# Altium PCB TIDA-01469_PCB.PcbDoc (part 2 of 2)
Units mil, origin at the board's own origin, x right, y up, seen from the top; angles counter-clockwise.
Board outline 2303.15 x 3751.97 mil, 4 copper layers (Layer 1 - Top Layer, Layer 2 - GND, Layer 3 - PWR, Layer 4 - Bottom Layer), stack 61.634 mil thick; 66 components, 33 nets, 183 pads, 184 vias.
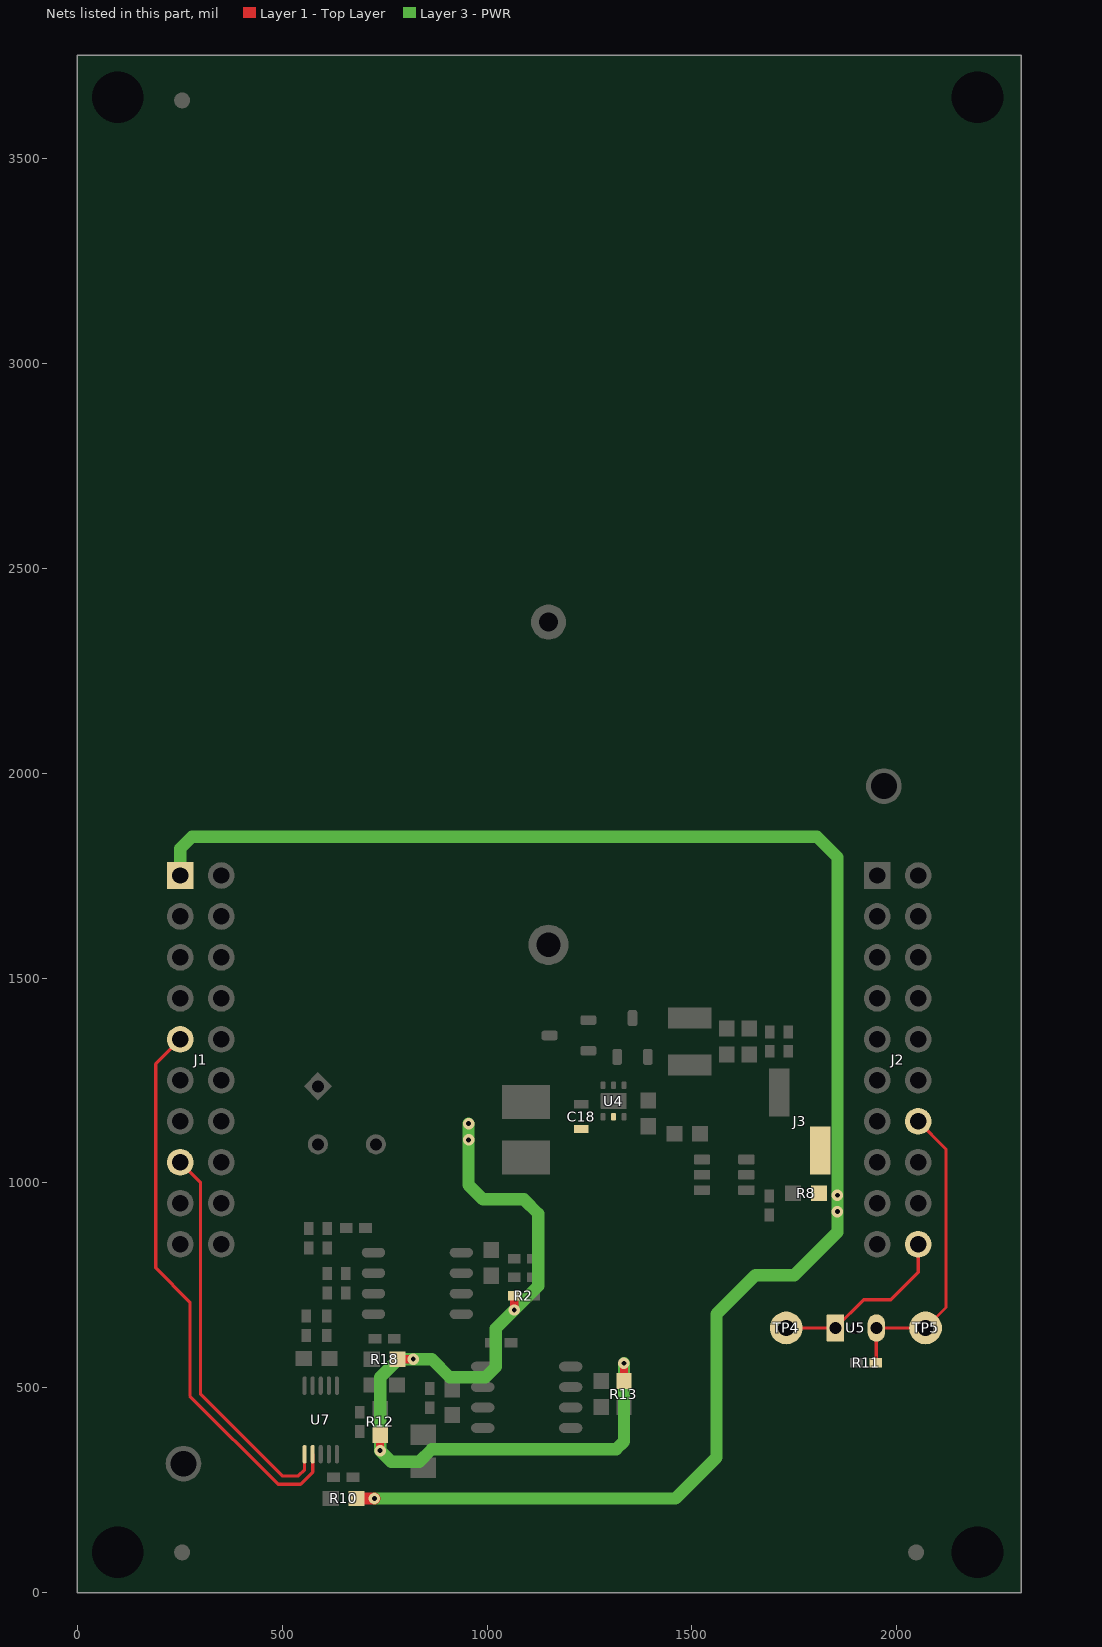
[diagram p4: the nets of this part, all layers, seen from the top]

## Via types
v1: diameter 28, hole 12, Layer 1 - Top Layer to Layer 4 - Bottom Layer, tented both sides, 178 vias
v2: diameter 50, hole 28, Layer 1 - Top Layer to Layer 4 - Bottom Layer, 4 vias
v3: diameter 19.68, hole 7.87, Layer 1 - Top Layer to Layer 4 - Bottom Layer, 2 vias

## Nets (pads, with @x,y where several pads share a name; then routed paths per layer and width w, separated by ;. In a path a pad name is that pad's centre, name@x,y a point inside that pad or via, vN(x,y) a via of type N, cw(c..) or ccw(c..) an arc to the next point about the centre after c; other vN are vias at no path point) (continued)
SPI_CS: J1.15 U7.6 | length 967.5
  Layer 1 - Top Layer w8: J1.15@251.3,1050.39 301,1000.69 301,484 500,285 539.8,285 554.8,300 U7.6@554.8,338.11
SPI_SDI: J1.9 U7.7 | length 1374.3
  Layer 1 - Top Layer w8: J1.9@251.3,1350.39 191.31,1290.41 191.31,792.7 275,709.02 275,480 490,265 545,265 574.49,294.49 U7.7@574.49,338.11
TEMP_IN: J2.20 TP4.1 U5.1 | length 446.7
  Layer 1 - Top Layer w8: TP4.1@1730.01,646.07 U5.1@1850.01,646.07 1918.94,715 1985,715 2052.09,782.09 J2.20@2052.09,850.39
TEMP_OUT: J2.14 R11.2 TP5.1 U5.2 | length 758.7
  Layer 1 - Top Layer w8: R11.2@1948.63,561.07 1950.01,562.45 U5.2@1950.01,646.07 TP5.1@2070.01,646.07 2120,696.06 2120,1082.48 J2.14@2052.09,1150.39
V_BATT: J1.1 J3.2 R8.1 R10.2 | length 4265
  Layer 1 - Top Layer w30: R10.2@681.5,230 v1(725,230)
  Layer 3 - PWR w30: J1.1@251.3,1750.39 251.3,1816.3 280,1845 1805,1845 1855,1795 v1(1855,970) v1(1855,930) 1855,880 1750,775 1655,775 1560,680 1560,330 1460,230 v1(725,230)
VCC: C18.1 R2.2 R12.2 R13.1 R18.2 U4.2 | length 2247.1
  Layer 1 - Top Layer w20: v1(739.09,346.77) R12.2@739.09,385.28 ; R18.2@781.5,570 v1(820,570) ; v1(1066.38,690) R2.2@1066.38,725 ; R13.1@1334.09,516.46 v1(1334.09,560)
  Layer 3 - PWR w30: v1(955,1145) v1(955,1105) 955,995 990,960 1090,960 1125,925 1125,748.62 v1(1066.38,690) 1021.22,644.84 1021.22,551.22 996.02,526.02 908.98,526.02 865,570 v1(820,570) 783.54,570 739.09,525.55 v1(739.09,346.77) 766.5,319.37 834.37,319.37 865,350 1315,350 1334.09,369.09 v1(1334.09,560)
pads on no net: FID1.1 FID2.1 FID3.1 J1.2 J1.3 J1.5 J1.6 J1.7 J1.8 J1.10 J1.11 J1.12 J1.14 J1.16 J1.17 J1.18 J1.19 J1.20 J2.1 J2.3 J2.4 J2.5 J2.6 J2.8 J2.9 J2.10 J2.11 J2.12 J2.13 J2.15 J2.16 J2.17 J2.18 J2.19 SH-J1.0 U3.3 U4.7@1290.96,1200 U4.7@1326.4,1200 U5.MH U6.1 U6.3 U6.7 U6.8

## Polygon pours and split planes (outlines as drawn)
GND on Layer 1 - Top Layer "Layer 1 - GND" (solid, remove dead copper, pour order 0): 20,20 2285,20 2285,3735 20,3735
GND on Layer 2 - GND "Layer 2 - GND" (solid, remove dead copper, pour order 2): 20,20 2285,20 2285,3735 20,3735
GND on Layer 3 - PWR "Layer 3 - GND" (solid, remove dead copper, pour order 4): 20,20 2285,20 2285,3735 20,3735
GND on Layer 4 - Bottom Layer "Layer 4 - GND" (solid, remove dead copper, pour order 6): 20,20 2285,20 2285,3735 20,3735

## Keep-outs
Keep-Out Layer:
  text ".Layer_Name" at 577,-858.49 h60

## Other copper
Layer 1 - Top Layer:
  pour cut-out: 587.5,1187.5 635,1235 587.5,1282.5 540,1235
  pour cut-out: 1982.84,600.33 1982.84,691.81 1816.67,691.81 1816.67,600.33
  region net GND: 560,485 536,461 520.99,461 520.99,544.51 541.49,544.51 560,526
  pour cut-out: 1755,1150 1887.24,1150 1887.24,1180 1755,1180
  pour cut-out: 1668.06,958.51 1668.06,1081.49 1516.49,1081.49 1492.47,1057.47 1492.47,958.51
  pour cut-out: 948.52,366.93 1246.81,366.93 1246.81,531.93 1161.81,531.93 1161.81,586.19 948.52,586.19
  pour cut-out: 745,665 980,665 980,800 1085,800 1085,835 1038.54,835 1038.54,855 980,855 895,855 745,855
  pour cut-out: 660,305 660,545 537.55,545 537.55,395 537.55,312.45 545,305
  region net VCC: 1305,1172 1302,1169 1302,1149 1295,1142 988,1142 970,1160 945,1160 935,1150 935,1100 945,1090 965,1090 990,1115 1294,1115 1315,1136 1315,1169 1312,1172
  region net GND: 1213,1180 1208,1185 1208,1217 1180,1245 1180,1310 1210,1340 1320,1340 1335,1325 1335,1295 1315,1275 1315,1225 1320,1220 1344,1220 1379,1255 1396,1255 1445,1206 1445,1189 1436,1180
  region net NetL1_2: 1290,1169 1290,1154 1288,1152 1002,1152 994,1160 994,1207 1032,1245 1159,1245 1197,1207 1197,1181 1206,1172 1287,1172
  region net NetC9_1: 1480,1080 1415,1015 1000,1015 985,1030 985,1090 1000,1105 1300,1105 1325,1130 1325,1166 1330,1171 1454,1171 1480,1145
  region net NetR9_1: 1495,1135 1505,1145 1545,1145 1555,1135 1555,1055 1545,1045 1505,1045 1495,1055
  region net NetC10_1: 1600,1025 1600,965 1615,950 1765,950 1770,955 1770,1022 1760,1032 1607,1032
  region net V_BATT: 1795,915 1785,925 1785,1140 1795,1150 1865,1150 1875,1140 1875,925 1865,915
  region net NetC4_1: 1380,1290 1510,1160 1750,1160 1770,1180 1770,1320 1750,1340 1395,1340 1380,1325
  region net NetQ1_2: 1225,1390 1240,1375 1360,1375 1375,1390 1375,1415 1360,1430 1240,1430 1225,1415
  region net NetBT1_1: 1095,1360 1115,1340 1185,1340 1205,1360 1203.25,1611.52 1185,1632.44 1115,1632.44 1095,1607.67
  region net NetC12_1: 613,363 608,358 608,268 590,250 590,215 600,205 635,205 645,215 645,358 640,363
  pour cut-out: 1968.37,1913 ccw(c1968.37,1968) 2023.37,1968 ccw(c1968.37,1968) 1968.37,2023 ccw(c1968.37,1968) 1913.37,1968 ccw(c1968.37,1968)
  pour cut-out: 1968.37,1913 ccw(c1968.37,1968) 2023.37,1968 ccw(c1968.37,1968) 1968.37,2023 ccw(c1968.37,1968) 1913.37,1968 ccw(c1968.37,1968)
  pour cut-out: 259.15,260 ccw(c259.15,315) 314.15,315 ccw(c259.15,315) 259.15,370 ccw(c259.15,315) 204.15,315 ccw(c259.15,315)
  pour cut-out: 259.15,260 ccw(c259.15,315) 314.15,315 ccw(c259.15,315) 259.15,370 ccw(c259.15,315) 204.15,315 ccw(c259.15,315)
  pour cut-out: 2052.09,1695.4 ccw(c2052.09,1750.4) 2107.09,1750.4 ccw(c2052.09,1750.4) 2052.09,1805.4 ccw(c2052.09,1750.4) 1997.09,1750.4 ccw(c2052.09,1750.4)
  pour cut-out: 351.3,1595.4 ccw(c351.3,1650.4) 406.3,1650.4 ccw(c351.3,1650.4) 351.3,1705.4 ccw(c351.3,1650.4) 296.3,1650.4 ccw(c351.3,1650.4)
  pour cut-out: 1150,2313.7 ccw(c1150,2368.7) 1205,2368.7 ccw(c1150,2368.7) 1150,2423.7 ccw(c1150,2368.7) 1095,2368.7 ccw(c1150,2368.7)
  text ".Layer_Name" at 577,-858.49 h60
Layer 2 - GND:
  pour cut-out: 587.5,1187.5 635,1235 587.5,1282.5 540,1235
  pour cut-out: 1968.5,1913.5 ccw(c1968.5,1968.5) 2023.5,1968.5 ccw(c1968.5,1968.5) 1968.5,2023.5 ccw(c1968.5,1968.5) 1913.5,1968.5 ccw(c1968.5,1968.5)
  pour cut-out: 259.29,260.5 ccw(c259.29,315.5) 314.29,315.5 ccw(c259.29,315.5) 259.29,370.5 ccw(c259.29,315.5) 204.29,315.5 ccw(c259.29,315.5)
  pour cut-out: 2052.09,1695.39 ccw(c2052.09,1750.39) 2107.09,1750.39 ccw(c2052.09,1750.39) 2052.09,1805.39 ccw(c2052.09,1750.39) 1997.09,1750.39 ccw(c2052.09,1750.39)
  pour cut-out: 351.3,1595.39 ccw(c351.3,1650.39) 406.3,1650.39 ccw(c351.3,1650.39) 351.3,1705.39 ccw(c351.3,1650.39) 296.3,1650.39 ccw(c351.3,1650.39)
  pour cut-out: 1150,2313.7 ccw(c1150,2368.7) 1205,2368.7 ccw(c1150,2368.7) 1150,2423.7 ccw(c1150,2368.7) 1095,2368.7 ccw(c1150,2368.7)
  text ".Layer_Name" at 577,-858.49 h60
Layer 3 - PWR:
  pour cut-out: 587.5,1187.5 635,1235 587.5,1282.5 540,1235
  pour cut-out: 1968.37,1913 ccw(c1968.37,1968) 2023.37,1968 ccw(c1968.37,1968) 1968.37,2023 ccw(c1968.37,1968) 1913.37,1968 ccw(c1968.37,1968)
  pour cut-out: 259.15,260 ccw(c259.15,315) 314.15,315 ccw(c259.15,315) 259.15,370 ccw(c259.15,315) 204.15,315 ccw(c259.15,315)
  pour cut-out: 2052.09,1695.39 ccw(c2052.09,1750.39) 2107.09,1750.39 ccw(c2052.09,1750.39) 2052.09,1805.39 ccw(c2052.09,1750.39) 1997.09,1750.39 ccw(c2052.09,1750.39)
  pour cut-out: 351.3,1595.39 ccw(c351.3,1650.39) 406.3,1650.39 ccw(c351.3,1650.39) 351.3,1705.39 ccw(c351.3,1650.39) 296.3,1650.39 ccw(c351.3,1650.39)
  pour cut-out: 1150,2313.7 ccw(c1150,2368.7) 1205,2368.7 ccw(c1150,2368.7) 1150,2423.7 ccw(c1150,2368.7) 1095,2368.7 ccw(c1150,2368.7)
  text ".Layer_Name" at 577,-858.49 h60
Layer 4 - Bottom Layer:
  pour cut-out: 587.5,1187.5 635,1235 587.5,1282.5 540,1235
  pour cut-out: 1968.37,1913 ccw(c1968.37,1968) 2023.37,1968 ccw(c1968.37,1968) 1968.37,2023 ccw(c1968.37,1968) 1913.37,1968 ccw(c1968.37,1968)
  pour cut-out: 259.15,260 ccw(c259.15,315) 314.15,315 ccw(c259.15,315) 259.15,370 ccw(c259.15,315) 204.15,315 ccw(c259.15,315)
  pour cut-out: 2052.09,1695.39 ccw(c2052.09,1750.39) 2107.09,1750.39 ccw(c2052.09,1750.39) 2052.09,1805.39 ccw(c2052.09,1750.39) 1997.09,1750.39 ccw(c2052.09,1750.39)
  pour cut-out: 351.3,1595.39 ccw(c351.3,1650.39) 406.3,1650.39 ccw(c351.3,1650.39) 351.3,1705.39 ccw(c351.3,1650.39) 296.3,1650.39 ccw(c351.3,1650.39)
  pour cut-out: 1150,2313.7 ccw(c1150,2368.7) 1205,2368.7 ccw(c1150,2368.7) 1150,2423.7 ccw(c1150,2368.7) 1095,2368.7 ccw(c1150,2368.7)
  text ".Layer_Name" at 577,-858.49 h60

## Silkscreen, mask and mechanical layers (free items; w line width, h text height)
Top Overlay:
  region: 1640,3585 1340,3585 1340,3485 1640,3485
  text "'.PRJ_Number'.PCB_Rev-" at 640,3500 h108.27
  text "GND" at 1910,1840 h60
  text "TEMP" at 1665.01,541.07 h60
  text "TEMP" at 2005.12,541.24 h60
  text "IN" at 1710.01,491.07 h60
  text "OUT" at 2025.01,491.07 h60
  text "GND" at 205,190 h60
  text ".Layer_Name" at 577,-858.49 h60
Bottom Overlay:
  text ".Layer_Name" at 577,-858.49 h60
Top Paste:
  text ".Layer_Name" at 577,-858.49 h60
Bottom Paste:
  text ".Layer_Name" at 577,-858.49 h60
Top Solder:
  text ".Layer_Name" at 577,-858.49 h60
  text ".Layer_Name" at 577,-858.49 h60
Bottom Solder:
  text ".Layer_Name" at 577,-858.49 h60
Drill Guide:
  text ".Layer_Name" at 577,-858.49 h60
M1 Board Outline:
  the board outline again, w10
  text ".Layer_Name" at 577,-858.49 h60
M2 Board Dimensions:
  rectangle: 125,-400 500,-275
  rectangle: 0,-275 125,-150
  lines w7: 0,-275 1000,-275 ; 125,-400 125,-150 ; 250,-400 250,-150 ; 500,-400 500,-150 ; 750,-400 750,-150 ; 0,-400 0,-150 1000,-150 1000,-400 0,-400
  text ".Layer_Name" at 577,-858.49 h60
M3 3D STEP Top:
  text ".Layer_Name" at 577,-858.49 h60
M4 3D STEP Bottom:
  text ".Layer_Name" at 577,-858.49 h60
M5 Assembly Top:
  lines w10: -292,-930.17 6308,-930.17 ; -292,-726.83 6310,-726.83 ; -292,-523.5 -292,-1133.5 3713,-1133.5 6310,-1133.5 6310,-523.5 -291.5,-523.5 -291.5,-1133.5 1284,-1133.5 ; 2173,-1133.5 2173,-523.5 ; 3440,-726.83 3440,-523.5 ; 4280,-726.83 4280,-523.5 ; 4902,-1140 4902,-937.17
  text "COMPONENTS MARKED 'DNP' SHOULD NOT BE POPULATED." at 1153.5,-318.5 h60
  text "ASSEMBLY VARIANT:" at 1153,-434 h60
  text ".VariantName" at 2189,-434 h60
  text "PCB VIEWED FROM TOP SIDE" at -228.5,-655.67 h60
  text "BOARD #:" at 2248,-655.67 h60
  text ".PRJ_Number" at 2793.5,-655.67 h60
  text "REV:" at 3638,-655.67 h60
  text ".PCB_Rev" at 3929.5,-655.67 h60
  text "SVN REV:" at 4476,-655.67 h60
  text ".VersionControl_RevNumber" at 4982,-655.67 h60
  text "TID #:" at 2248,-859 h60
  text ".TID" at 2793.5,-859 h60
  text "PLOT NAME =" at -228.5,-1064.34 h60
  text ".plot_File_Name" at 577,-1064.34 h60
  text "GENERATED    :" at 2250,-1064.34 h60
  text ".Print_Date" at 3119.5,-1064.34 h60
  text ".Print_Time" at 3848.5,-1064.34 h60
  text "TEXAS INSTRUMENTS" at 5113,-1064.34 h60
M6 Assembly Bottom:
  lines w10: -292.5,-727.33 6309.5,-727.33 ; -290.5,-930.67 6309.5,-930.67 ; 1115.5,-1140.5 1115.5,-937.67 ; 1737.5,-727.33 1737.5,-524 ; 2577.5,-727.33 2577.5,-524 ; 3844.5,-1134 3844.5,-524 ; 4733.5,-1134 6309,-1134 6309,-524 -292.5,-524 -292.5,-1134 2304.5,-1134 6309.5,-1134 6309.5,-524
  text "COMPONENTS MARKED 'DNP' SHOULD NOT BE POPULATED." at 6102,-318 h60
  text ".VariantName" at 5058,-434 h60
  text "ASSEMBLY VARIANT:" at 6097,-434 h60
  text ".VersionControl_RevNumber" at 1035.5,-656.17 h60
  text "SVN REV:" at 1541.5,-656.17 h60
  text ".PCB_Rev" at 2088,-656.17 h60
  text "REV:" at 2379.5,-656.17 h60
  text ".PRJ_Number" at 3224,-656.17 h60
  text "BOARD #:" at 3769.5,-656.17 h60
  text "PCB VIEWED FROM BOTTOM SIDE" at 6246,-656.17 h60
  text ".TID" at 3224,-859.5 h60
  text "TID #:" at 3769.5,-859.5 h60
  text "TEXAS INSTRUMENTS" at 904.5,-1064.84 h60
  text ".Print_Time" at 2169,-1064.84 h60
  text ".Print_Date" at 2898,-1064.84 h60
  text "GENERATED    :" at 3767.5,-1064.84 h60
  text ".plot_File_Name" at 5440.5,-1064.84 h60
  text "PLOT NAME =" at 6246,-1064.84 h60
M9 Title Sheet:
  drawing of 1178 lines, arcs and shapes, not listed
  text "1" at 739.84,8036.5 h70
  text "2" at 3235.5,8036.5 h70
  text "3" at 5724.84,8036.5 h70
  text "4" at 8231.51,8036.5 h70
  text "5" at 10730.5,8036.5 h70
  text "6" at 13235.5,8036.5 h70
  text "A" at -416.5,6893.5 h70
  text "A" at 14383.5,6893.5 h70
  text "B" at -416.5,4513.5 h70
  text "B" at 14383.5,4513.5 h70
  text "C" at -416.5,2138.5 h70
  text "C" at 14383.5,2138.5 h70
  text "PROJECT TITLE:" at 11343.5,277.5 h45
  text ".PRJ_Title" at 11393.5,144.17 h60
  text "DESIGNED FOR:" at 11343.5,-23.5 h45
  text ".PRJ_Customer" at 11393.5,-163.5 h70
  text "D" at -416.5,-231.5 h70
  text "D" at 14383.5,-231.5 h70
  text "FILE NAME:" at 11343.5,-323.5 h45
  text ".PCB_File_Name_No_Path" at 11393.5,-443.5 h70
  text "Texas Instruments (TI) and/or its licensors do not warrant the accuracy or completeness of this specification" at 6374,-605.34 h45
  text "ENGINEER:" at 11343.5,-613.5 h45
  text "LAYOUT BY:" at 12848.5,-613.5 h45
  text "or any information contained therein. TI and/or its licensors do not warrant that this design will meet" at 6329.01,-718 h45
  text ".PRJ_Engineer" at 11393.5,-768.49 h70
  text "JMM" at 12852,-800 h100
  text "s  o  l  u  t  i  o  n  s" at 13710,-803 h68
  text "the specifications, will be suitable for your application or fit for any particular purpose, or will operate in" at 6329.01,-830.67 h45
  text ".Layer_Name" at 577,-858.49 h60
  text "ALTIUM DESIGNER VERSION:" at 12848.5,-923.5 h45
  text "an implementation. TI and/or its licensors do not warrant that the design is production worthy. You should" at 6329.01,-943.33 h45
  text "completely validate and test your design implementation to confirm the system functionality for your application." at 6374,-1056 h45
  text ".print_Scale" at 11393.5,-1056.83 h70
  text ".Application_BuildNumber" at 12899,-1056.83 h70
  text "1" at 739.84,-1263.5 h70
  text "2" at 3235.5,-1263.5 h70
  text "3" at 5724.84,-1263.5 h70
  text "4" at 8231.51,-1263.5 h70
  text "5" at 10730.5,-1263.5 h70
  text "6" at 13235.5,-1263.5 h70
M10 Fab Notes:
  drawing of 173 lines, arcs and shapes, not listed
  text "DESIGN INFORMATION" at 12378.02,6201 h60
  text "MIN. TRACK WIDTH:" at 11733.46,6021 h60
  text "8" at 12829.7,6021 h60
  text "MIL" at 12984.46,6021 h60
  text "MIN. CLEARANCE:" at 11733.46,5889 h60
  text "0.2" at 12769.7,5889 h60
  text "mm" at 12984.46,5889 h60
  text "MIN. VIA PAD SIZE:" at 11733.46,5757 h60
  text "28" at 12799.71,5757 h60
  text "MIL" at 12984.46,5757 h60
  text "0.05mm (2MIL)" at 12428.46,5615.29 h60
  text "MINIMUM ANNULAR RING" at 11404.23,5611 h60
  text "EXTERNAL" at 13136.46,5611 h60
  text "PER" at 11604.23,5493 h60
  text "IPC-D-275 CLASS 2 LEVEL C" at 11824.23,5493 h60
  text "MIL, HOLES" at 13312.46,5380.71 h60
  text "+/-" at 12920,5380 h60
  text "+/-" at 13774,5380 h60
  text "REGISTRATION TOLERANCES:" at 11404.23,5375 h60
  text "METAL" at 12604,5375 h60
  text "5" at 13180.2,5375 h60
  text "3" at 14013.2,5375 h60
  text "MIL" at 14129.46,5375 h60
  text "+/-" at 13774,5262 h60
  text "HOLE SIZE TOLERANCE (UNLESS OTHERWISE SPECIFIED):" at 11404.23,5257 h60
  text "3" at 14013.2,5257 h60
  text "MIL" at 14129.46,5257 h60
  text "MATERIAL:" at 11329.46,5047.54 h60
  text "FR-4 High Tg" at 12315.9,4907.21 h60
  text "FR-408" at 11750.46,4898.64 h60
  text "OTHER" at 13238.46,4898.64 h60
  text "X" at 12161,4895 h60
  text "62 MIL (1.6mm) +/-10%" at 12070.56,4735.92 h60
  text "THICKNESS:" at 11404.23,4731.64 h60
  text "X" at 11942.4,4731.64 h60
  text "OTHER" at 13355.46,4731.64 h60
  text "TOLERANCE:" at 11404.23,4573.64 h60
  text "X" at 12243.53,4573.64 h60
  text "ANSI IPC-6012 TYPE 3 CLASS 2" at 12430.48,4573.64 h60
  text "OTHER +/-" at 12430.46,4417.64 h60
  text "BOW & TWIST:" at 11404.23,4260.64 h60
  text "X" at 12243.53,4260.64 h60
  text "ANSI IPC-6012 TYPE 3 CLASS 2" at 12430.48,4260.64 h60
  text "OTHER +/-" at 12430.46,4102.13 h60
  text "DRILLING:" at 11329.46,3963.64 h60
  text "REFERENCE:" at 11404.23,3846.64 h60
  text "X" at 12052.46,3846.64 h60
  text "AS SHOWN" at 12239.46,3846.64 h60
  text "X" at 12953.46,3846.64 h60
  text "NC_DRILL FILES" at 13090.46,3846.64 h60
  text "PTH COPPER THICKNESS:" at 11404.23,3688.64 h60
  text "X" at 12534.46,3688.64 h60
  text "20-30 um" at 12671.46,3688.64 h60
  text "OTHER" at 13388.46,3688.64 h60
  text "BOARD FINISH:" at 11329.46,3529.64 h60
  text "SILKSCREEN:" at 11484.68,3411.64 h60
  text "X" at 12433.46,3411.64 h60
  text "TOP" at 12559.46,3411.64 h60
  text "X" at 12943.46,3411.64 h60
  text "BOTTOM" at 13070.46,3411.64 h60
  text "SILKSCREEN COLOR:" at 11484.68,3244.64 h60
  text "X" at 12432.42,3244.64 h60
  text "WHITE" at 12559.46,3244.64 h60
  text "OTHER" at 13070.46,3244.64 h60
  text "X" at 12563.42,3085.44 h60
  text "GREEN" at 12690.46,3085.44 h60
  text "OTHER" at 13308.46,3085.44 h60
  text "SOLDER RESIST COLOR:" at 11484.68,3074.64 h60
  text "X" at 12563.42,2915.44 h60
  text "MATTE" at 12690.46,2915.44 h60
  text "SEMI-GLOSS" at 13308,2914.8 h60
  text "IMMERSION GOLD (ENIG)" at 12390.46,2726.92 h60
  text "ENEPIG" at 13728,2723.64 h60
  text "SURFACE FINISH:" at 11329.46,2722.64 h60
  text "X" at 12203.51,2722.64 h60
  text "IMM. TIN/SILVER OR EQUIV" at 11659,2565.64 h60
  text "OTHER" at 13090.46,2565.64 h60
  text "ARRAY/PANEL:" at 11329.46,2386.64 h60
  text "CUT AND TRIM PER M1 BOARD OUTLINE" at 12390.46,2382.35 h60
  text "N.C. ROUTE" at 12390.46,2230.64 h60
  text "X" at 13069.46,2230.64 h60
  text "V. SCORE" at 13256.46,2230.64 h60
  text "CERTIFICATION:" at 11329.46,2093.64 h60
  text "MATERIALS AND WORKMANSHIP FOR ALL PCBS" at 12054.46,2093.64 h60
  text "TO MEET OR EXCEED THE REQUIREMENTS OF:" at 12054.46,1995.64 h60
  text "X" at 11680.96,1859.13 h60
  text "ANSI IPC-A-600F CLASS ->" at 11819.96,1859.13 h60
  text "X" at 13459.02,1859.13 h60
  text "2" at 13577.96,1859.14 h60
  text "1" at 13262.96,1857.64 h60
  text "3" at 13931.96,1857.64 h60
  text "X" at 12495.02,1699.64 h60
  text "RoHS" at 12631.96,1699.64 h60
  text "OTHER" at 13276.36,1699.64 h60
  text "PER ORDER" at 13673.42,1699.64 h60
  text "ALL BOARDS MUST MEET OR EXCEED UL94-V0 REQUIREMENTS." at 11357,1534 h60
  text "PCB MUST BEAR THE UL94V-0 UL REGISTERED MATERIAL ID NUMBER" at 11357,1414 h60
  text "ADDITIONAL REQUIREMENTS:" at 11329.46,1240.64 h60
  text "MICROSECTION:" at 11404.23,1125.64 h60
  text "YES" at 12309.96,1125.64 h60
  text "REQUIRED" at 13171.46,969.49 h60
  text "BARE BOARD ELEC. TEST:" at 11404.23,966.64 h60
  text "NONE" at 12709.96,966.64 h60
  text "X" at 13044.46,966.64 h60
  text "PER ORDER" at 13763.46,966.64 h60
  text ".Layer_Name" at 577,-858.49 h60
M11 Gerber Information:
  lines w10: -292,-930.17 6308,-930.17 ; -292,-726.83 6310,-726.83 ; -292,-523.5 -292,-1133.5 3713,-1133.5 6310,-1133.5 6310,-523.5 -291.5,-523.5 -291.5,-1133.5 1284,-1133.5 ; 2173,-1133.5 2173,-523.5 ; 3440,-726.83 3440,-523.5 ; 4280,-726.83 4280,-523.5 ; 4902,-1140 4902,-937.17
  text "ALL ARTWORK VIEWED FROM TOP SIDE" at -228.5,-655.67 h60
  text "BOARD #:" at 2248,-655.67 h60
  text ".PRJ_Number" at 2793.5,-655.67 h60
  text "REV:" at 3638,-655.67 h60
  text ".PCB_Rev" at 3929.5,-655.67 h60
  text "SVN REV:" at 4476,-655.67 h60
  text ".VersionControl_RevNumber" at 4982,-655.67 h60
  text "LAYER NAME =" at -228.5,-858.49 h60
  text "TID #:" at 2248,-859 h60
  text ".TID" at 2793.5,-859 h60
  text "PLOT NAME =" at -228.5,-1064.34 h60
  text ".plot_File_Name" at 577,-1064.34 h60
  text "GENERATED    :" at 2250,-1064.34 h60
  text ".Print_Date" at 3119.5,-1064.34 h60
  text ".Print_Time" at 3848.5,-1064.34 h60
  text "TEXAS INSTRUMENTS" at 5113,-1064.34 h60
M12 Stackup:
  drawing of 295 lines, arcs and shapes, not listed
  text "Layer" at 9292.5,7827.5 h60
  text "Name" at 9702.41,7827.5 h60
  text "Material" at 11112,7827.5 h60
  text "Thickness" at 11971.77,7827.5 h60
  text "Constant" at 12621.6,7827.5 h60
  text "Board Layer Stack" at 13191.47,7827.5 h60
  text "1" at 9292.5,7707.5 h60
  text "Top Overlay" at 9702.41,7707.5 h60
  text "2" at 9292.5,7587.5 h60
  text "Top Solder" at 9702.41,7587.5 h60
  text "Solder Resist" at 11112,7587.5 h60
  text "0.40mil" at 11971.77,7587.5 h60
  text "3.5" at 12621.6,7587.5 h60
  text "3" at 9292.5,7467.5 h60
  text "Layer 1 - Top Layer" at 9702.41,7467.5 h60
  text "Copper" at 11112,7467.5 h60
  text "1.40mil" at 11971.77,7467.5 h60
  text "4" at 9292.5,7347.5 h60
  text "Dielectric 1" at 9702.41,7347.5 h60
  text "FR-4" at 11112,7347.5 h60
  text "10.00mil" at 11971.77,7347.5 h60
  text "4.2" at 12621.6,7347.5 h60
  text "5" at 9292.5,7227.5 h60
  text "Layer 2 - GND" at 9702.41,7227.5 h60
  text "Copper" at 11112,7227.5 h60
  text "1.42mil" at 11971.77,7227.5 h60
  text "6" at 9292.5,7107.5 h60
  text "Dielectric 2" at 9702.41,7107.5 h60
  text "FR-4" at 11112,7107.5 h60
  text "36.00mil" at 11971.77,7107.5 h60
  text "4.2" at 12621.6,7107.5 h60
  text "7" at 9292.5,6987.5 h60
  text "Layer 3 - PWR" at 9702.41,6987.5 h60
  text "Copper" at 11112,6987.5 h60
  text "1.42mil" at 11971.77,6987.5 h60
  text "8" at 9292.5,6867.5 h60
  text "Dielectric 3" at 9702.41,6867.5 h60
  text "FR-4" at 11112,6867.5 h60
  text "10.00mil" at 11971.77,6867.5 h60
  text "4.2" at 12621.6,6867.5 h60
  text "9" at 9292.5,6747.5 h60
  text "Layer 4 - Bottom Layer" at 9702.41,6747.5 h60
  text "Copper" at 11112,6747.5 h60
  text "1.40mil" at 11971.77,6747.5 h60
  text "10" at 9292.5,6627.5 h60
  text "Bottom Solder" at 9702.41,6627.5 h60
  text "Solder Resist" at 11112,6627.5 h60
  text "0.40mil" at 11971.77,6627.5 h60
  text "3.5" at 12621.6,6627.5 h60
  text "11" at 9292.5,6507.5 h60
  text "Bottom Overlay" at 9702.41,6507.5 h60
  text ".Layer_Name" at 577,-858.49 h60
M13 Component Bodies Top:
  text ".Layer_Name" at 577,-858.49 h60
M14 Component Bodies Bottom:
  text ".Layer_Name" at 577,-858.49 h60
M15 Courtyards Top:
  text ".Layer_Name" at 577,-858.49 h60
M16 Courtyards Bottom:
  text ".Layer_Name" at 577,-858.49 h60
Drill Drawing:
  circle w10: c2885.62,235.83 r20
  circle w10: c2885.62,235.83 r33.33
  lines w10: 2852.29,352.5 2918.96,352.5 2918.96,419.17 2852.29,419.17 2852.29,352.5 ; 2852.29,569.17 2918.96,569.17 2885.62,502.5 2852.29,569.17 ; 2852.29,719.17 2918.96,719.17 2885.62,652.5 2852.29,719.17 ; 2852.29,802.5 2918.96,802.5 2918.96,869.17 2852.29,869.17 2852.29,802.5 ; 2852.29,969.17 2868.96,969.17 2868.96,952.5 2902.29,952.5 2902.29,969.17 2918.96,969.17 2918.96,1002.5 2902.29,1002.5 2902.29,1019.17 2868.96,1019.17 2868.96,1002.5 2852.29,1002.5 2852.29,969.17 ; 2852.29,1135.83 2885.62,1102.5 2918.96,1135.83 2885.62,1169.17 2852.29,1135.83 ; 2852.29,1269.17 2868.96,1269.17 2885.62,1252.5 2902.29,1269.17 2918.96,1269.17 2902.29,1285.83 2918.96,1302.5 2902.29,1302.5 2885.62,1319.17 2868.96,1302.5 2852.29,1302.5 2868.96,1285.83 2852.29,1269.17 ; 2852.29,1402.5 2885.62,1419.17 2918.96,1402.5 2902.29,1435.83 2918.96,1469.17 2885.62,1452.5 2852.29,1469.17 2868.96,1435.83 2852.29,1402.5 ; 2852.29,1552.5 2852.29,1569.17 2868.96,1585.83 2852.29,1602.5 2852.29,1619.17 2868.96,1619.17 2885.62,1602.5 2902.29,1619.17 2918.96,1619.17 2918.96,1602.5 2902.29,1585.83 2918.96,1569.17 2918.96,1552.5 2902.29,1552.5 2885.62,1569.17 2868.96,1552.5 2852.29,1552.5 ; 2865.62,705.83 2905.62,705.83 2885.62,665.83 2865.62,705.83 ; 2865.62,815.83 2905.62,815.83 2905.62,855.83 2865.62,855.83 2865.62,815.83
  lines w15: 2792.5,157.5 6377.56,157.5 ; 2792.5,1657.5 6377.56,1657.5 ; 3343.38,7.5 3343.38,1807.5 ; 3943.22,7.5 3943.22,1807.5 ; 5092.88,7.5 5092.88,1807.5 ; 5598.76,7.5 5598.76,1807.5 ; 2792.5,7.5 6377.56,7.5 6377.56,1807.5 2792.5,1807.5 2792.5,7.5
  text "Symbol" at 2882.5,1702.5 h72
  text "Count" at 3388.38,1702.5 h72
  text "Hole Size" at 3988.22,1702.5 h72
  text "Plated" at 5137.88,1702.5 h72
  text "Hole Type" at 5643.76,1702.5 h72
  text "1" at 3388.38,1552.5 h60
  text "29.53mil (0.750mm)" at 3988.22,1552.5 h60
  text "NPTH" at 5137.88,1552.5 h60
  text "Round" at 5643.76,1552.5 h60
  text "1" at 3388.38,1402.5 h60
  text "46.50mil (1.181mm)" at 3988.22,1402.5 h60
  text "PTH" at 5137.88,1402.5 h60
  text "Round" at 5643.76,1402.5 h60
  text "1" at 3388.38,1252.5 h60
  text "59.06mil (1.500mm)" at 3988.22,1252.5 h60
  text "PTH" at 5137.88,1252.5 h60
  text "Round" at 5643.76,1252.5 h60
  text "2" at 3388.38,1102.5 h60
  text "7.87mil (0.200mm)" at 3988.22,1102.5 h60
  text "PTH" at 5137.88,1102.5 h60
  text "Round" at 5643.76,1102.5 h60
  text "2" at 3388.38,952.5 h60
  text "63.00mil (1.600mm)" at 3988.22,952.5 h60
  text "PTH" at 5137.88,952.5 h60
  text "Round" at 5643.76,952.5 h60
  text "4" at 3388.38,802.5 h60
  text "28.00mil (0.711mm)" at 3988.22,802.5 h60
  text "PTH" at 5137.88,802.5 h60
  text "Round" at 5643.76,802.5 h60
  text "4" at 3388.38,652.5 h60
  text "125.98mil (3.200mm)" at 3988.22,652.5 h60
  text "NPTH" at 5137.88,652.5 h60
  text "Round" at 5643.76,652.5 h60
  text "5" at 3388.38,502.5 h60
  text "29.53mil (0.750mm)" at 3988.22,502.5 h60
  text "PTH" at 5137.88,502.5 h60
  text "Round" at 5643.76,502.5 h60
  text "42" at 3388.38,352.5 h60
  text "40.00mil (1.016mm)" at 3988.22,352.5 h60
  text "PTH" at 5137.88,352.5 h60
  text "Round" at 5643.76,352.5 h60
  text "178" at 3388.38,202.5 h60
  text "12.00mil (0.305mm)" at 3988.22,202.5 h60
  text "PTH" at 5137.88,202.5 h60
  text "Round" at 5643.76,202.5 h60
  text "240 Total" at 3388.38,52.5 h60
  text ".Layer_Name" at 577,-858.49 h60
M17 Embedded Cavity:
  text ".Layer_Name" at 577,-858.49 h60
M18 Embedded Assembly:
  text ".Layer_Name" at 577,-858.49 h60
M19 Embedded Keepout:
  text ".Layer_Name" at 577,-858.49 h60

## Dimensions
0,0 to 0,3751.97 on M2 Board Dimensions
0,0 to 2303.15,0 on M2 Board Dimensions
0,-400 to 1000,-400 on M2 Board Dimensions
